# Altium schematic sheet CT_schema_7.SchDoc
size 284 x 245 mm
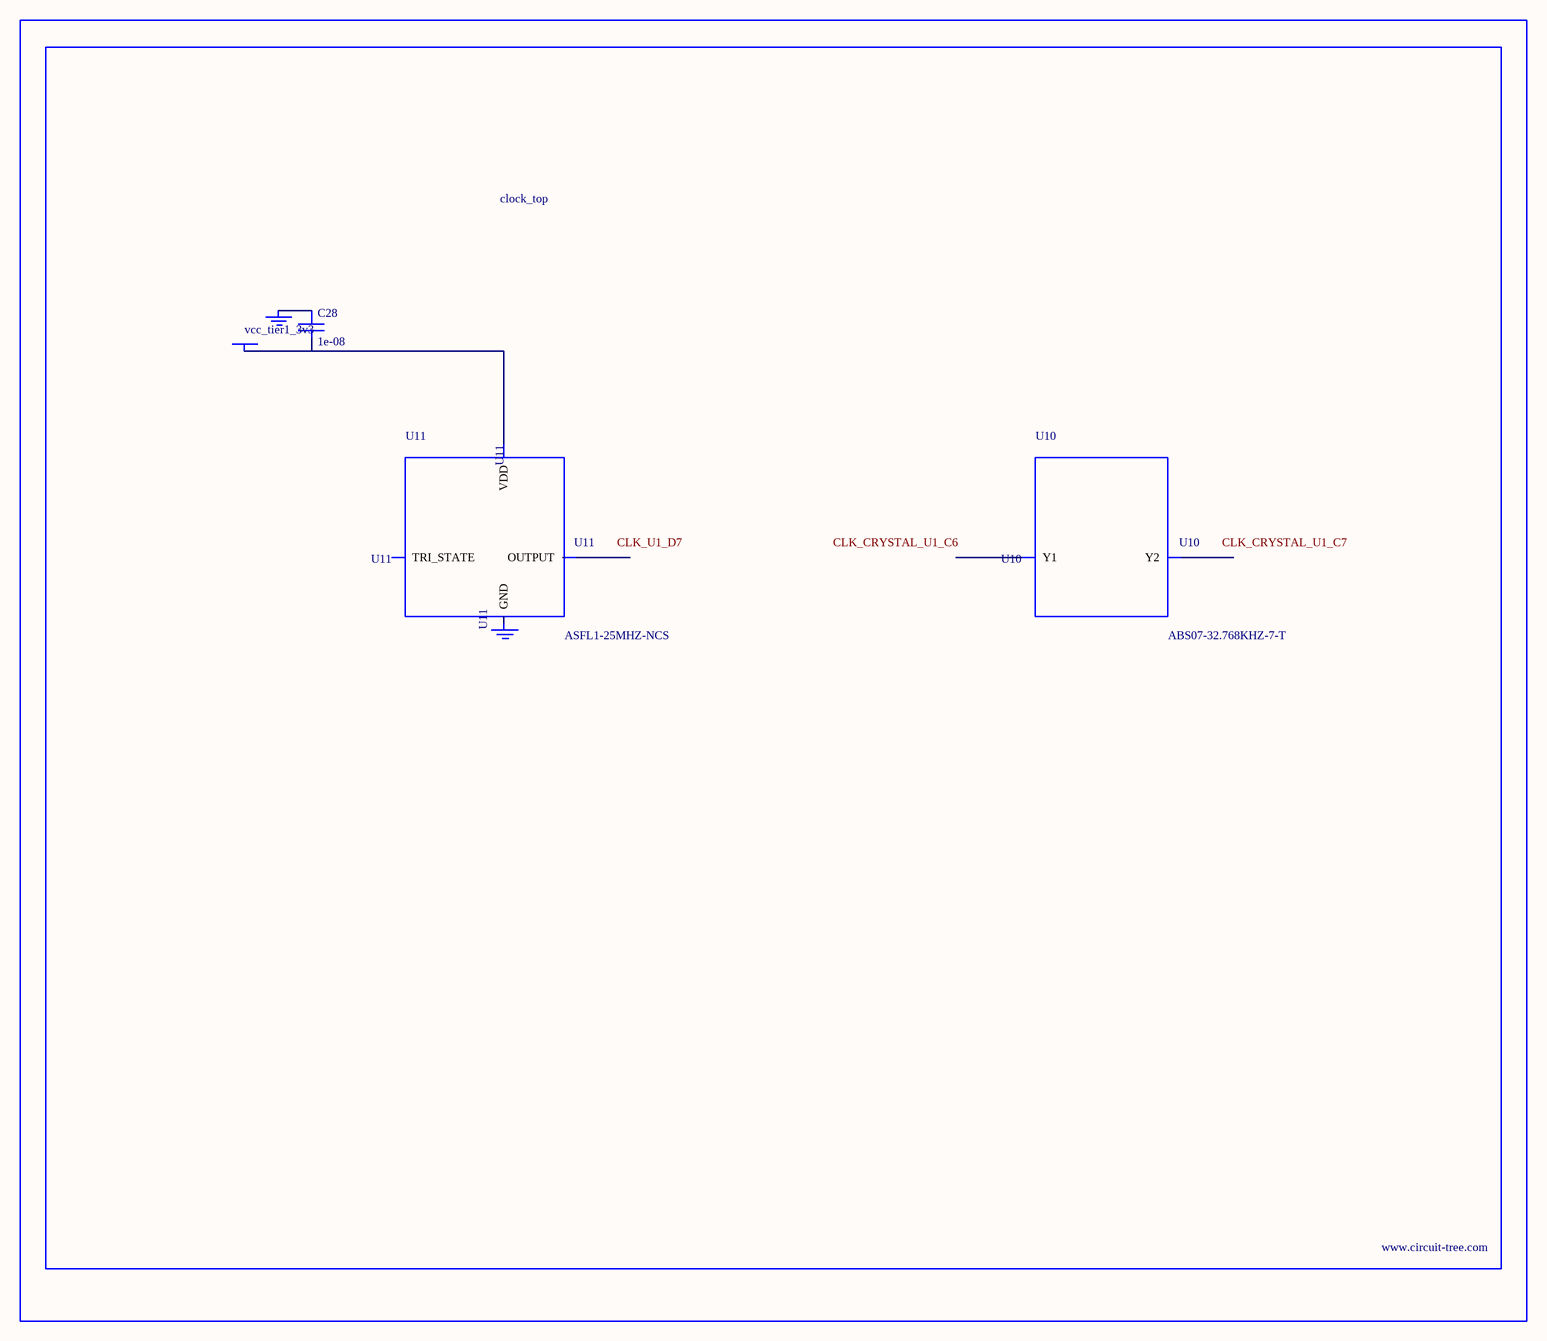
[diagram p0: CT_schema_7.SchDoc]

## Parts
BORDER6  (no value)
C28  1e-08  [C0402]
GND_INSTANCE_6_0  (no value)
GND_INSTANCE_6_1  (no value)
POWER_INSTANCE_6_0  vcc_tier1_3v3
U10  ABS07-32.768KHZ-7-T  [ABS07-32.768KHZ-7-T]
U11  ASFL1-25MHZ-NCS  [ASFL1]

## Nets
NetC28_1: C28.1 GND_INSTANCE_6_0.0(GND)
NetC28_2: C28.2 POWER_INSTANCE_6_0.0(PWR) U11.4(VDD)

Not connected (* = marked no-connect by the designer): GND_INSTANCE_6_1 0(GND); U10 1(Y1) 2(Y2); U11 1(TRI_STATE) 2(GND) 3(OUTPUT)

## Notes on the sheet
- Labels drawn without touching a wire or pin: CLK_CRYSTAL_U1_C6, CLK_CRYSTAL_U1_C7, CLK_U1_D7

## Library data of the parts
BORDER6 = BORDER_PAGE6
C28 = C0402C103K3RAC
GND_INSTANCE_6_0 GND_INSTANCE_6_1 = GND
POWER_INSTANCE_6_0 = PWR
